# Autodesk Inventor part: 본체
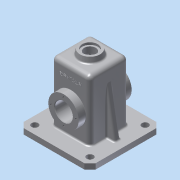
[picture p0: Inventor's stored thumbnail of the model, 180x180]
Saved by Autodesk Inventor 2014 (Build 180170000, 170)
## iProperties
Created: 2016-02
Part Number: 본체
Material: 알루미늄 6061
Document SubType Name: Modeling
Designer: SCD-A13
Density: 2.71 g/cm^3
Appearance: 알루미늄 - 평지
Mass: 1029.35 g
Surface Area: 1031.46 cm^2
Volume: 379.835 cm^3
Author: SCD-A13
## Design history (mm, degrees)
sketch "스케치1"
  geometry: C1 r 27.5 at (0, 0); 1 further point
  constraints: 1 centre point, 1 coincident
  dimensions: "d0" = 55 diameter of C1
extrude "돌출1" new body sketch "스케치1" stored distance "d1" = 96; taper "d2" = 0 deg
sketch "스케치2"
  geometry: L1 (-35, 35)-(35, 35); L2 (35, 35)-(35, -35); L3 (35, -35)-(-35, -35); L4 (-35, -35)-(-35, 35); 3 further points
  constraints: 8 end point, 2 midpoint, 2 parallel, 1 horizontal, 1 horizontal alignment, 1 perpendicular, 1 vertical alignment
  dimensions: "d3" = 70 distance of L1.start L1.end; "d4" = 70 distance of L1.end L2.end
extrude "돌출2" join sketch "스케치2" distance "d5" = 65; taper "d7" = 0 deg; dims "d6" = 55, "d8" = 0
sketch "스케치3"
  geometry: C1 r 20 at (0, 0); 1 further point
  constraints: 1 centre point, 1 coincident
  dimensions: "d9" = 40 diameter of C1
extrude "돌출3" join sketch "스케치3" distance "d10" = 10; taper "d11" = 0 deg
feature "면 기울기1" dims angle "d12" = 10 deg
sketch "스케치4"
  geometry: L1 (35, 35)-(-35, 35) reference; L2 (-35, 35)-(-35, -35) reference; L3 (-35, -35)-(35, -35) reference; L4 (35, -35)-(35, 35) reference; L5 (-65, 65)-(65, 65); L6 (65, 65)-(65, -65); L7 (65, -65)-(-65, -65); L8 (-65, -65)-(-65, 65); 3 further points
  constraints: 8 end point, 2 midpoint, 2 parallel, 1 horizontal, 1 horizontal alignment, 1 perpendicular, 1 vertical alignment
  dimensions: "d13" = 130 distance of L5.start L5.end; "d14" = 130 distance of L5.end L6.end
extrude "돌출4" join sketch "스케치4" distance "d15" = 10; taper "d16" = 0 deg
chamfer "모따기1" distance "d17" = 10; stored, may be unused: second distance "d18" = 2, angle "d19" = 45 deg
hole "구멍1" diameter "d22" = 21; stored, may be unused: countersink angle "d26" = 90 deg, drill point angle "d28" = 118 deg; dims "d20" = 10, "d21" = 10, "d23" = 6, "d24" = 28, "d25" = 4, "d27" = 8
hole "구멍2" diameter "d31" = 32; stored, may be unused: countersink angle "d35" = 90 deg, drill point angle "d37" = 118 deg; dims "d29" = 10, "d30" = 10, "d32" = 6, "d33" = 28, "d34" = 4, "d36" = 8
sketch "스케치5"
  geometry: L1 (-30, 30)-(30, 30); L2 (30, 30)-(30, -30); L3 (30, -30)-(-30, -30); L4 (-30, -30)-(-30, 30); C1 r 10.5 at (0, 0) reference; 2 further points
  constraints: 8 end point, 2 midpoint, 2 parallel, 1 horizontal, 1 horizontal alignment, 1 perpendicular, 1 vertical alignment
  dimensions: "d38" = 60 distance of L1.start L1.end; "d39" = 60 distance of L1.end L2.end
extrude "돌출5" cut sketch "스케치5" distance "d40" = 115; taper "d41" = 0 deg
sketch "스케치6"
  geometry: L1 (-65, -45)-(-35, -45) reference; L2 (-35, -45)-(-35, -27.5) reference; L3 (-35, -27.5)-(-48, -27.5) reference; L4 (-48, -27.5)-(-48, -16) reference; L5 (-48, -16)-(-30, -16) reference; L6 (-30, -16)-(-30, -55) reference; L7 (-30, -55)-(-65, -55) reference; L8 (-65, -55)-(-65, -45) reference; L9 (35, -45)-(65, -45) reference; L10 (65, -45)-(65, -55) reference; L11 (65, -55)-(30, -55) reference; L12 (30, -55)-(30, -16) reference; L13 (30, -16)-(48, -16) reference; L14 (48, -16)-(48, -27.5) reference; L15 (48, -27.5)-(35, -27.5) reference; L16 (35, -27.5)-(35, -45) reference; L17 (18.237, 75)-(20, 65) reference; L18 (20, 65)-(35, 65) reference; L19 (35, 65)-(35, 27.5) reference; L20 (35, 27.5)-(48, 27.5) reference; L21 (48, 27.5)-(48, 16) reference; L22 (48, 16)-(30, 16) reference; L23 (30, 16)-(30, 60) reference; L24 (30, 60)-(10.5, 60) reference; L25 (10.5, 60)-(10.5, 71) reference; L26 (10.5, 71)-(14, 71) reference; L27 (14, 71)-(14, 75) reference; L28 (14, 75)-(18.237, 75) reference; L29 (-35, 27.5)-(-35, 65) reference; L30 (-35, 65)-(-20, 65) reference; L31 (-20, 65)-(-18.237, 75) reference; L32 (-18.237, 75)-(-14, 75) reference; L33 (-14, 75)-(-14, 71) reference; L34 (-14, 71)-(-10.5, 71) reference; L35 (-10.5, 71)-(-10.5, 60) reference; L36 (-10.5, 60)-(-30, 60) reference; L37 (-30, 60)-(-30, 16) reference; L38 (-30, 16)-(-48, 16) reference; L39 (-48, 16)-(-48, 27.5) reference; L40 (-48, 27.5)-(-35, 27.5) reference; L41 (-30, 16)-(-23, 16); L42 (-23, 16)-(-23, 20.5); L43 (-23, 20.5)-(-30, 27.5); L44 (0, 0)-(-48, 0)
  constraints: 8 end point, 2 perpendicular, 1 parallel, 1 point on line
  dimensions: "d43" = 55 diameter of L43.end L44; "d44" = 135 deg angle of L43 L37; "d45" = 7 distance between parallel lines of L42 L37
revolve "회전1" sketch "스케치6" stored, may be unused: angle "d46" = 90 deg
sketch "스케치7"
  geometry: L1 (65, -55)-(65, 55) reference; L2 (55, 65)-(-55, 65) reference; 5 further points
  constraints: 2 horizontal alignment, 2 vertical alignment
  dimensions: "d47" = 100 distance of point (50, 50) point (-50, 50); "d48" = 15 distance from line of point (50, 50) L1; "d49" = 100 distance of point (50, -50) point (50, 50); "d50" = 15 distance from line of L2 point (50, 50)
hole "구멍3" sketch "스케치7" at (-50, 50), (50, 50), (50, -50), (-50, -50) diameter "d51" = 12; stored, may be unused: countersink angle "d55" = 90 deg, drill point angle "d57" = 118 deg; dims "d52" = 6, "d53" = 28, "d54" = 4, "d56" = 8
fillet "모깎기1" dims "d58" = 0.5
sketch "스케치8"
  geometry: C1 r 16 at (0, 0) reference; 1 further point
  constraints: 1 vertical alignment
  dimensions: "d59" = 22.5 distance of C1.centre point (0, 22.5)
hole "구멍4" sketch "스케치8" at (0, 22.5) diameter "d60" = 3.242; stored, may be unused: countersink angle "d64" = 90 deg, drill point angle "d66" = 118 deg; dims "d61" = 8, "d62" = 28, "d63" = 4, "d65" = 10
fillet "모깎기2" dims "d70" = 0.5
sketch "스케치9"
  geometry: L1 (65, 20)-(75, 18.237) reference; L2 (75, 18.237)-(75, 14) reference; L3 (75, 14)-(71, 14) reference; L4 (71, 14)-(71, 10.5) reference; L5 (71, 10.5)-(60, 10.5) reference; L6 (60, 10.5)-(60, 30) reference; L7 (60, 30)-(-55, 30) reference; L8 (-55, 30)-(-55, 65) reference; L9 (-55, 65)-(-45, 65) reference; L10 (-45, 65)-(-45, 35) reference; L11 (-45, 35)-(65, 35) reference; L12 (65, 35)-(65, 20) reference; L13 (75, -18.237)-(65, -20) reference; L14 (65, -20)-(65, -35) reference; L15 (65, -35)-(-45, -35) reference; L16 (-45, -35)-(-45, -65) reference; L17 (-45, -65)-(-55, -65) reference; L18 (-55, -65)-(-55, -30) reference; L19 (-55, -30)-(60, -30) reference; L20 (60, -30)-(60, -10.5) reference; L21 (60, -10.5)-(71, -10.5) reference; L22 (71, -10.5)-(71, -14) reference; L23 (71, -14)-(75, -14) reference; L24 (75, -14)-(75, -18.237) reference; L25 (-45, 50)-(40.069, 35); L26 (65, 20)-(75, 18.237) reference; L27 (75, 18.237)-(75, 14) reference; L28 (75, 14)-(71, 14) reference; L29 (71, 14)-(71, 10.5) reference; L30 (71, 10.5)-(60, 10.5) reference; L31 (60, 30)-(-55, 30) reference; L32 (-55, 30)-(-55, 65) reference; L33 (-55, 65)-(-45, 65) reference; L34 (-45, 65)-(-45, 35) reference; L35 (-45, 35)-(65, 35) reference; L36 (65, 35)-(65, 20) reference; L37 (75, -18.237)-(65, -20) reference; L38 (65, -20)-(65, -35) reference; L39 (65, -35)-(-45, -35) reference; L40 (-45, -35)-(-45, -65) reference; L41 (-45, -65)-(-55, -65) reference; L42 (-55, -65)-(-55, -30) reference; L43 (-55, -30)-(60, -30) reference; L44 (60, -10.5)-(71, -10.5) reference; L45 (71, -10.5)-(71, -14) reference; L46 (71, -14)-(75, -14) reference; L47 (75, -14)-(75, -18.237) reference; L48 (60, 10.5)-(60, 30) reference; L49 (60, -30)-(60, -10.5) reference; 1 further point
  constraints: 2 end point, 1 midpoint, 1 point on line
  dimensions: "d71" = 10 deg angle of L9 L25; "d97" = 15 distance from line of L25.start L9
feature "리브1" sketch "스케치9" dims "d73" = 1, "d74" = 10, "d75" = 0, "d76" = 0, "d77" = 1, "d78" = 1
sketch "스케치10"
  geometry: L1 (70, 0)-(70, -110) reference; L2 (53.237, 10)-(16.763, 10) reference; 1 further point
  constraints: 1 other
  dimensions: "d79" = 30 distance from line of point (35, -20) L2; "d80" = 35 distance from line of point (35, -20) L1
feature "엠보싱1" sketch "스케치10" dims "d1" = 96, "d81" = 0.5, "d82" = 0
fillet "모깎기5" dims "d87" = 3
fillet "모깎기6" dims "d88" = 8
fillet "모깎기7" dims "d89" = 8, "d90" = 3
fillet "모깎기8" dims "d91" = 3
chamfer "모따기2" distance "d92" = 1; stored, may be unused: second distance "d93" = 2, angle "d94" = 45 deg
fillet "모깎기9" dims "d95" = 3
fillet "모깎기10" dims "d96" = 0.5
node "솔리드1"
pattern_circular "원형 패턴1" dims angle "d68" = 360 deg
mirror "대칭1"
mirror "대칭2"
node "절단 모서리 투영1"
node "절단 모서리 투영2"
node "절단 모서리 투영3"
